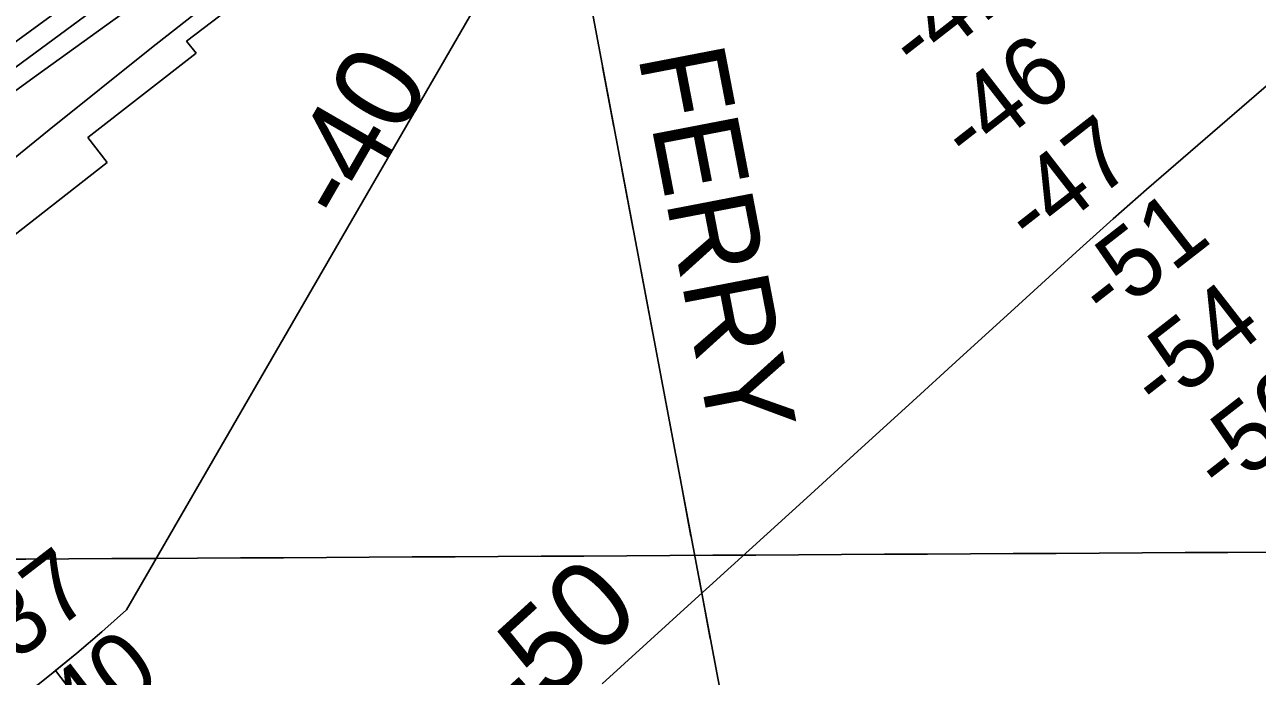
# Model space of a CAD drawing. Extents: x 3477039 to 3515015, y 546746 to 572297.
# Drawn here: x 3482058 to 3483241, y 558060 to 558686 of the extents above; entities that cross this region are included whole.
import ezdxf

# ---------------------------------------------------------------- set-up
doc = ezdxf.new("R2010")
doc.units = 0
for name, color, linetype in [('V-GRID-MAJR', 7, 'Continuous'), ('V-RIVR-FERY', 7, 'Continuous'), ('V-RIVR-RANG', 7, 'Continuous'), ('V-RRAP-RVMT', 7, 'Continuous'), ('V-TOPO-DPTH', 7, 'Continuous'), ('V-TOPO-MAJR', 7, 'Continuous'), ('V-TOPO-MAJR-IDEN', 7, 'Continuous'), ('V-TOPO-MINR', 7, 'Continuous'), ('V-TOPO-MINR-IDEN', 7, 'Continuous')]:
    doc.layers.add(name, color=color, linetype=linetype)

msp = doc.modelspace()

# ---------------------------------------------------------------- linework, layer by layer
at = {"layer": 'V-GRID-MAJR'}
msp.add_spline([(3481235.517, 558168.281), (3486509.202, 558197.813), (3491782.883, 558228.111), (3497056.56, 558259.177), (3502330.233, 558291.01), (3507603.9, 558323.61), (3512877.563, 558356.976), (3512877.5640000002, 558356.976)], degree=3, dxfattribs=at)
at = {"layer": 'V-RIVR-FERY'}
for points in [[(3483030.9420000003, 556427.919), (3482556.165, 558946.53)], [(3482623.81, 558587.681), (3482613.0100000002, 558644.9720000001)], [(3482642.316, 558489.51), (3482631.5160000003, 558546.801)], [(3482660.822, 558391.339), (3482650.022, 558448.63)], [(3482679.328, 558293.1680000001), (3482668.528, 558350.459)], [(3482697.8340000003, 558194.997), (3482687.034, 558252.2880000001)], [(3482716.34, 558096.826), (3482705.54, 558154.117)]]:
    msp.add_lwpolyline(points, dxfattribs=at)
at = {"layer": 'V-RRAP-RVMT'}
for p, q in [((3482213.775969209, 558669.8503937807), (3482305.1850000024, 558739.2960000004)), ((3482222.9050000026, 558658.1250000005), (3482213.775969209, 558669.8503937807)), ((3482118.9310000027, 558577.2500000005), (3482222.9050000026, 558658.1250000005)), ((3482137.4360000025, 558553.3940000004), (3482118.9310000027, 558577.2500000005)), ((3482027.0810000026, 558467.0240000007), (3482137.4360000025, 558553.3940000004))]:
    msp.add_line(p, q, dxfattribs=at)
at = {"layer": 'V-TOPO-DPTH'}
for points in [[(3483466.8524723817, 559602.0502040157), (3483079.910446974, 559323.5326334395), (3483013.904200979, 559276.2357664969), (3482947.7640958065, 559229.1276916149), (3482881.4232018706, 559182.3028048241), (3482814.9484487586, 559135.666710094), (3482706.406110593, 559059.8633355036), (3482694.138504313, 559051.2199466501), (3482681.919392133, 559042.5091266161), (3482669.7730211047, 559033.6971598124), (3482657.675144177, 559024.8177618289), (3482479.5450852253, 558892.9355173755), (3482378.9351569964, 558817.3982824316), (3482279.0137450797, 558740.9732386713), (3482180.125107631, 558663.2164816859), (3482081.9249864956, 558584.571915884), (3481895.685325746, 558433.3611713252), (3481878.6389912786, 558419.3319762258), (3481861.7192994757, 558405.1536763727), (3481844.98957167, 558390.7517193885), (3481828.386486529, 558376.20065765), (3481238.632533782, 557604.5494533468)], [(3481238.632533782, 557604.5494533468), (3481828.386486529, 558376.20065765), (3481844.98957167, 558390.7517193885), (3481861.7192994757, 558405.1536763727), (3481878.6389912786, 558419.3319762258), (3481895.685325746, 558433.3611713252), (3482081.9249864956, 558584.571915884), (3482180.125107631, 558663.2164816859), (3482279.0137450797, 558740.9732386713), (3482378.9351569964, 558817.3982824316), (3482479.5450852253, 558892.9355173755), (3482657.675144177, 559024.8177618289), (3482669.7730211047, 559033.6971598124), (3482681.919392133, 559042.5091266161), (3482694.138504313, 559051.2199466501), (3482706.406110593, 559059.8633355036), (3482814.9484487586, 559135.666710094), (3482881.4232018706, 559182.3028048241), (3482947.7640958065, 559229.1276916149), (3483013.904200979, 559276.2357664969), (3483079.910446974, 559323.5326334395), (3483466.8524723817, 559602.0502040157)], [(3483463.2694503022, 559574.2323240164), (3482731.9231120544, 559044.4637824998), (3482726.4144089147, 559040.4901593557), (3482720.8951994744, 559036.5312451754), (3482715.3602305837, 559032.5943944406), (3482709.8147553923, 559028.6722526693), (3482700.6731050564, 559022.2339832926), (3482699.693671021, 559021.537746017), (3482696.784259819, 559019.4092595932), (3482683.943151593, 559009.792212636), (3482676.6095107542, 559004.2018459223), (3482669.3409008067, 558998.5295922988), (3482662.169837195, 558992.7345083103), (3482655.0638044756, 558986.8575374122), (3482156.2461014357, 558124.2803388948), (3482132.4504724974, 558103.2540266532), (3482108.3596948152, 558082.5792732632), (3482083.8261940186, 558062.4318581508), (3482058.997544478, 558042.6360018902)], [(3482088.119734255, 558065.9578016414), (3482108.3596948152, 558082.5792732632), (3482132.4504724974, 558103.2540266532), (3482156.2461014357, 558124.2803388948), (3482655.0638044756, 558986.8575374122), (3482662.169837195, 558992.7345083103), (3482669.3409008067, 558998.5295922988), (3482676.6095107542, 559004.2018459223), (3482683.943151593, 559009.792212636), (3482696.784259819, 559019.4092595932), (3482699.693671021, 559021.537746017), (3482700.6731050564, 559022.2339832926), (3482709.8147553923, 559028.6722526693), (3482715.3602305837, 559032.5943944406), (3482720.8951994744, 559036.5312451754), (3482726.4144089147, 559040.4901593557), (3482731.9231120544, 559044.4637824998), (3483463.2694503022, 559574.2323240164)], [(3483284.5759181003, 559525.8238625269), (3482685.762905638, 559129.908751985), (3482679.020613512, 559125.4589283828), (3482672.2734624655, 559121.0164977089), (3482665.5190230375, 559116.5851564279), (3482658.7597246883, 559112.1612080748), (3482648.687963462, 559105.5810684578), (3482646.9641110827, 559104.4479208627), (3482645.2445378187, 559103.3083553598), (3482641.8225077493, 559101.0035527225), (3482638.4140467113, 559098.6785886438), (3482638.0607827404, 559098.4303613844), (3482637.708667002, 559098.1804878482), (3482630.2402644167, 559092.8413998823), (3482626.159063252, 559089.9148563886), (3482622.0835347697, 559086.9804582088), (3482618.0165153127, 559084.0342780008), (3482613.955168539, 559081.0802431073), (3481836.769406, 558514.0701134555)], [(3481836.769406, 558514.0701134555), (3482613.955168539, 559081.0802431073), (3482618.0165153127, 559084.0342780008), (3482622.0835347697, 559086.9804582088), (3482626.159063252, 559089.9148563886), (3482630.2402644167, 559092.8413998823), (3482637.708667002, 559098.1804878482), (3482638.0607827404, 559098.4303613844), (3482638.4140467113, 559098.6785886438), (3482641.8225077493, 559101.0035527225), (3482645.2445378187, 559103.3083553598), (3482646.9641110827, 559104.4479208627), (3482648.687963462, 559105.5810684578), (3482658.7597246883, 559112.1612080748), (3482665.5190230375, 559116.5851564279), (3482672.2734624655, 559121.0164977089), (3482679.020613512, 559125.4589283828), (3482685.762905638, 559129.908751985), (3483284.5759181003, 559525.8238625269)], [(3482028.39058261, 558606.9837559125), (3482069.7151299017, 558636.8956093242), (3482616.619787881, 559031.032857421), (3482640.4793368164, 559048.1171290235), (3482664.407816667, 559065.1036679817), (3482688.4396928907, 559081.9436079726), (3482712.5405000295, 559098.6858153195), (3482985.113551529, 559286.8026359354), (3483071.135946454, 559346.4959858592), (3483156.9533880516, 559406.4809634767), (3483242.463399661, 559466.9033826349)], [(3482028.39058261, 558606.9837559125), (3482069.7151299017, 558636.8956093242), (3482616.619787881, 559031.032857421), (3482640.4793368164, 559048.1171290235), (3482664.407816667, 559065.1036679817), (3482688.4396928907, 559081.9436079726), (3482712.5405000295, 559098.6858153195), (3482985.113551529, 559286.8026359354), (3483071.135946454, 559346.4959858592), (3483156.9533880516, 559406.4809634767), (3483242.463399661, 559466.9033826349)], [(3482058.997544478, 558042.6360018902), (3482083.8261940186, 558062.4318581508), (3482085.805202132, 558064.0570602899)], [(3482085.805202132, 558064.0570602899), (3482088.119734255, 558065.9578016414), (3482209.608844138, 557906.7565973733), (3482205.4901715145, 557904.0244511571), (3482161.9228517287, 557875.1238079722), (3482141.151150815, 557858.5841595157), (3482141.122433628, 557846.9705228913), (3482142.743965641, 557832.0346034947), (3482153.503405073, 557823.7124930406), (3482161.793624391, 557822.862443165), (3482180.0407220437, 557824.4764244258), (3482204.114972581, 557835.2010528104), (3482259.7347220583, 557859.9500375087), (3482304.5847759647, 557888.8734052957), (3482342.807167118, 557920.3018130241), (3482358.6137618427, 557941.0014914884), (3482359.469654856, 557951.7835321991), (3482358.6711962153, 557964.228764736), (3482348.740983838, 557972.5488247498), (3482333.827204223, 557977.5630055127), (3482316.407282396, 557975.117428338), (3482256.6106292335, 557937.9355137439), (3482209.608844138, 557906.7565973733), (3482088.119734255, 558065.9578016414)]]:
    msp.add_lwpolyline(points, dxfattribs=at)
at = {"layer": 'V-TOPO-MAJR'}
msp.add_lwpolyline([(3483317.9643607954, 558685.2131934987), (3483135.0768040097, 558527.378314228), (3483118.9373090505, 558513.3313601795), (3483102.877089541, 558499.1950978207), (3483086.935783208, 558484.9248729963), (3483071.0737523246, 558470.5653398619), (3483004.876375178, 558410.132229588), (3482955.9593212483, 558365.5064981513), (3482907.0211997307, 558320.9038986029), (3482858.0514768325, 558276.3359968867), (3482809.0606863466, 558231.7912270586), (3482698.479755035, 558131.3173203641), (3482655.547519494, 558092.3216332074), (3482612.606947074, 558053.335131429)], dxfattribs=at)
at = {"layer": 'V-TOPO-MINR'}
for points in [[(3483466.8524723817, 559602.0502040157), (3483079.910446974, 559323.5326334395), (3483013.904200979, 559276.2357664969), (3482947.7640958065, 559229.1276916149), (3482881.4232018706, 559182.3028048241), (3482814.9484487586, 559135.666710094), (3482706.406110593, 559059.8633355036), (3482694.138504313, 559051.2199466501), (3482681.919392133, 559042.5091266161), (3482669.7730211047, 559033.6971598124), (3482657.675144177, 559024.8177618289), (3482479.5450852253, 558892.9355173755), (3482378.9351569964, 558817.3982824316), (3482279.0137450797, 558740.9732386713), (3482180.125107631, 558663.2164816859), (3482081.9249864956, 558584.571915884), (3481895.685325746, 558433.3611713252), (3481878.6389912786, 558419.3319762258), (3481861.7192994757, 558405.1536763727), (3481844.98957167, 558390.7517193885), (3481828.386486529, 558376.20065765), (3481238.632533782, 557604.5494533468)], [(3483463.2694503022, 559574.2323240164), (3482731.9231120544, 559044.4637824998), (3482726.4144089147, 559040.4901593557), (3482720.8951994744, 559036.5312451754), (3482715.3602305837, 559032.5943944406), (3482709.8147553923, 559028.6722526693), (3482700.6731050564, 559022.2339832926), (3482699.693671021, 559021.537746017), (3482696.784259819, 559019.4092595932), (3482683.943151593, 559009.792212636), (3482676.6095107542, 559004.2018459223), (3482669.3409008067, 558998.5295922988), (3482662.169837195, 558992.7345083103), (3482655.0638044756, 558986.8575374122), (3482156.2461014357, 558124.2803388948), (3482132.4504724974, 558103.2540266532), (3482108.3596948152, 558082.5792732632), (3482083.8261940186, 558062.4318581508), (3482058.997544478, 558042.6360018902)], [(3483284.5759181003, 559525.8238625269), (3482685.762905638, 559129.908751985), (3482679.020613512, 559125.4589283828), (3482672.2734624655, 559121.0164977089), (3482665.5190230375, 559116.5851564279), (3482658.7597246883, 559112.1612080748), (3482648.687963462, 559105.5810684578), (3482646.9641110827, 559104.4479208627), (3482645.2445378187, 559103.3083553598), (3482641.8225077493, 559101.0035527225), (3482638.4140467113, 559098.6785886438), (3482638.0607827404, 559098.4303613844), (3482637.708667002, 559098.1804878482), (3482630.2402644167, 559092.8413998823), (3482626.159063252, 559089.9148563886), (3482622.0835347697, 559086.9804582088), (3482618.0165153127, 559084.0342780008), (3482613.955168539, 559081.0802431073), (3481836.769406, 558514.0701134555)], [(3483256.1553166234, 559490.3389779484), (3483196.7604338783, 559449.3133780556), (3483137.171212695, 559408.5670160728), (3482716.7730354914, 559123.2795781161), (3482684.909037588, 559101.526858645), (3482653.1263012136, 559079.656744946), (3482621.4654571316, 559057.6105399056), (3482589.8858745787, 559035.4469406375), (3482495.3691951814, 558968.7196734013), (3482416.767907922, 558912.8609398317), (3482338.4008456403, 558856.6776370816), (3482260.385120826, 558800.0074805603), (3482182.6036209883, 558743.012754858), (3481832.433169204, 558484.7445140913), (3481822.337800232, 558477.2704138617), (3481812.260577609, 558469.7720184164), (3481802.2105745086, 558462.2371801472), (3481792.178717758, 558454.6780466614), (3481236.257806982, 558034.2042330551)], [(3483242.463399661, 559466.9033826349), (3483156.9533880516, 559406.4809634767), (3483071.135946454, 559346.4959858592), (3482985.113551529, 559286.8026359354), (3482712.5405000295, 559098.6858153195), (3482688.4396928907, 559081.9436079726), (3482664.407816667, 559065.1036679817), (3482640.4793368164, 559048.1171290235), (3482616.619787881, 559031.032857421), (3482069.7151299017, 558636.8956093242), (3482028.39058261, 558606.9837559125)]]:
    msp.add_lwpolyline(points, dxfattribs=at)

# ---------------------------------------------------------------- texts
at = {"layer": 'V-RIVR-FERY'}
msp.add_text('FERRY', height=82.99983200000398, rotation=280.89694459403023, dxfattribs=at).set_placement((3482646.731893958, 558656.1903036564))
at = {"layer": 'V-RIVR-RANG'}
for s, height, rotation, p in [('-41', 67.00000000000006, 37.90733333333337, (3482914.956806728, 558636.7670674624)), ('-46', 67.00000000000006, 37.90733333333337, (3482965.1692619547, 558549.1257550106)), ('-47', 67.00000000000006, 37.90733333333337, (3483026.195819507, 558469.9044359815)), ('-51', 67.00000000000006, 37.90733333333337, (3483097.0218188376, 558398.3145674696)), ('-54', 67.00000000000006, 37.90733333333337, (3483147.44239755, 558310.835317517)), ('-50', 67.00000000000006, 37.90733333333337, (3483207.853903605, 558231.1340675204)), ('-37', 67.00000000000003, 37.55430555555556, (3482025.660485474, 558055.4363566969)), ('-40', 67.00000000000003, 37.55430555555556, (3482088.9342658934, 557977.9448806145))]:
    msp.add_text(s, height=height, rotation=rotation, dxfattribs=at).set_placement(p)
at = {"layer": 'V-TOPO-MAJR-IDEN'}
msp.add_text('-50', height=83.00000000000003, rotation=42.25830596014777, dxfattribs=at).set_placement((3482533.5980155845, 558011.0247829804))
at = {"layer": 'V-TOPO-MINR-IDEN'}
msp.add_text('-40', height=83, rotation=59.95973727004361, dxfattribs=at).set_placement((3482368.9276322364, 558492.1084020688))

doc.saveas('drawing.dxf')
